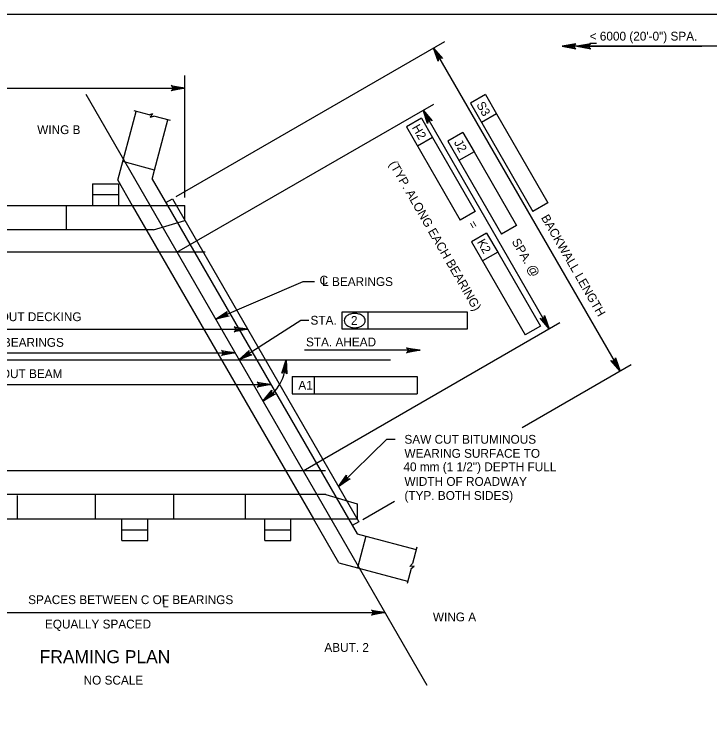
# Model space of a CAD drawing. Extents: x -13 to 81, y -176 to 0.
# Drawn here: x 13.18 to 22.65, y -164.52 to -154.75 of the extents above; entities that cross this region are included whole.
import ezdxf

# ---------------------------------------------------------------- set-up
doc = ezdxf.new("R2010")
doc.units = 0
for name, color, linetype in [('Level 1', 7, 'Continuous'), ('Level 2', 7, 'Continuous'), ('Level 3', 7, 'Continuous'), ('Level 4', 7, 'Continuous')]:
    doc.layers.add(name, color=color, linetype=linetype)

msp = doc.modelspace()

# ---------------------------------------------------------------- linework, layer by layer
at = {"layer": 'Level 1'}
msp.add_lwpolyline([(1.75, -175.25), (33.25, -175.25), (33.25, -154.75), (1.75, -154.75)], close=True, dxfattribs=at)
at = {"layer": 'Level 2'}
for p, q in [((14.5927, -157.0093), (14.8438, -156.0722)), ((15.0924, -156.8711), (15.2755, -156.1879)), ((15.0924, -156.8711), (14.6607, -156.7554)), ((15.06, -156.9921), (15.0924, -156.8711)), ((14.5927, -157.0093), (14.79, -157.3512)), ((15.06, -156.9921), (15.2673, -157.3512)), ((14.2487, -157.0558), (14.2487, -157.3512)), ((14.2487, -157.0558), (14.6031, -157.0558)), ((14.6031, -157.0558), (14.6031, -157.3512)), ((15.2452, -157.3129), (15.3347, -157.2612)), ((15.3347, -157.2612), (17.8734, -161.6584)), ((7.3205, -157.3512), (15.5059, -157.3512)), ((14.79, -157.3512), (17.2547, -161.6202)), ((15.2673, -157.3512), (17.7321, -161.6202)), ((15.5059, -157.5578), (15.5059, -157.3512)), ((15.0767, -157.6833), (15.5059, -157.5578)), ((15.0767, -157.6833), (7.7497, -157.6833)), ((17.4221, -161.288), (10.0952, -161.288)), ((17.4221, -161.288), (17.8513, -161.4135)), ((17.8513, -161.4135), (17.8513, -161.6202)), ((9.6659, -161.6202), (17.8513, -161.6202)), ((14.6453, -161.9155), (14.6453, -161.6202)), ((14.9997, -161.9155), (14.9997, -161.6202)), ((16.5942, -161.9155), (16.5942, -161.6202)), ((16.9485, -161.9155), (16.9485, -161.6202)), ((17.5999, -162.2181), (17.2547, -161.6202)), ((17.7321, -161.6202), (17.8485, -161.822)), ((17.8734, -161.6584), (17.7839, -161.7101)), ((17.8485, -161.822), (17.9695, -161.8544)), ((14.6453, -161.9155), (14.9997, -161.9155)), ((16.5942, -161.9155), (16.9485, -161.9155)), ((17.9695, -161.8544), (17.8538, -162.2862)), ((17.9695, -161.8544), (18.6527, -162.0374)), ((17.5999, -162.2181), (18.537, -162.4692))]:
    msp.add_line(p, q, dxfattribs=at)
at = {"layer": 'Level 3'}
for p, q in [((14.1551, -155.8382), (18.7996, -163.8826)), ((15.0182, -156.119), (14.8132, -156.0641)), ((15.0182, -156.119), (15.0663, -156.0983)), ((15.0663, -156.0983), (15.0334, -156.1482)), ((15.0334, -156.1482), (15.0848, -156.1368)), ((15.3088, -156.1968), (15.0848, -156.1368)), ((14.2487, -157.2035), (14.6031, -157.2035)), ((13.8944, -157.6833), (13.8944, -157.3512)), ((13.2272, -161.6202), (13.2272, -161.3036)), ((14.2902, -161.6202), (14.2902, -161.288)), ((15.354, -161.6202), (15.354, -161.288)), ((16.3284, -161.6202), (16.3284, -161.288)), ((14.6453, -161.7678), (14.9997, -161.7678)), ((16.5942, -161.7678), (16.9485, -161.7678)), ((18.6617, -162.0041), (18.6017, -162.2281)), ((18.5837, -162.2947), (18.5288, -162.4998)), ((18.566, -162.2669), (18.6017, -162.2281)), ((18.6258, -162.2633), (18.566, -162.2669)), ((18.5837, -162.2947), (18.6258, -162.2633))]:
    msp.add_line(p, q, dxfattribs=at)
at = {"layer": 'Level 4'}
for p, q in [((15.388, -157.2305), (19.0423, -155.1207)), ((23.5655, -155.1843), (20.6404, -155.1843)), ((20.9797, -155.1843), (22.5397, -155.1843)), ((21.1059, -155.146), (21.0173, -155.146)), ((18.8889, -155.2092), (21.4276, -159.6064)), ((15.5059, -157.2456), (15.5059, -155.5842)), ((7.3205, -155.7548), (15.5059, -155.7548)), ((19.5953, -155.8435), (19.3908, -155.9616)), ((19.5953, -155.8435), (19.7466, -156.1054)), ((15.3975, -157.99), (18.893, -155.9718)), ((19.3908, -155.9616), (20.2412, -157.4345)), ((20.4622, -159.0314), (18.7463, -156.0565)), ((18.7252, -156.1655), (18.5206, -156.2837)), ((18.7252, -156.1655), (18.8763, -156.4274)), ((19.7466, -156.1054), (19.542, -156.2235)), ((19.7466, -156.1054), (20.4458, -157.3164)), ((18.5206, -156.2837), (19.2521, -157.5507)), ((19.2892, -156.3587), (19.0846, -156.4768)), ((19.2892, -156.3587), (19.4404, -156.6207)), ((18.8763, -156.4274), (18.6717, -156.5456)), ((18.8763, -156.4274), (19.4567, -157.4326)), ((19.0846, -156.4768), (19.8162, -157.7439)), ((19.4404, -156.6207), (19.2358, -156.7387)), ((19.4404, -156.6207), (20.0207, -157.6258)), ((20.4458, -157.3164), (20.2412, -157.4345)), ((19.4567, -157.4326), (19.2521, -157.5507)), ((20.0207, -157.6258), (19.8162, -157.7439)), ((19.6115, -157.7273), (19.4069, -157.8455)), ((19.6115, -157.7273), (19.7627, -157.9892)), ((19.4069, -157.8455), (20.1384, -159.1126)), ((15.7792, -157.99), (3.7627, -157.99)), ((19.7627, -157.9892), (19.5581, -158.1074)), ((19.7627, -157.9892), (20.343, -158.9944)), ((15.9238, -158.9017), (17.1136, -158.3895)), ((17.1136, -158.3895), (17.268, -158.3895)), ((17.6477, -159.0373), (17.6477, -158.8011)), ((17.6477, -158.8011), (17.9977, -158.8011)), ((17.9977, -159.0373), (17.9977, -158.8011)), ((17.9977, -158.8011), (19.3486, -158.8011)), ((19.3486, -158.8011), (19.3486, -159.0373)), ((16.2413, -159.456), (17.0821, -158.915)), ((17.0821, -158.915), (17.1917, -158.915)), ((17.1146, -160.9642), (20.6102, -158.946)), ((20.343, -158.9944), (20.1384, -159.1126)), ((8.2945, -159.0381), (16.3606, -159.0381)), ((19.3486, -159.0373), (17.6477, -159.0373)), ((8.8385, -159.3603), (16.1886, -159.3603)), ((18.7082, -159.3248), (17.1333, -159.3248)), ((6.2433, -159.4554), (18.3055, -159.4554)), ((20.0965, -160.3749), (21.581, -159.5178)), ((16.9645, -159.6822), (17.267, -159.6822)), ((16.9645, -159.6822), (16.9645, -159.9184)), ((17.267, -159.6822), (17.267, -159.9184)), ((17.267, -159.6822), (18.6653, -159.6822)), ((18.6653, -159.6822), (18.6653, -159.9184)), ((8.8488, -159.7914), (16.6762, -159.7914)), ((16.9645, -159.9184), (18.6653, -159.9184)), ((17.5973, -161.1802), (18.2556, -160.5326)), ((18.2556, -160.5326), (18.369, -160.5326)), ((17.4195, -160.9642), (3.7506, -160.9642)), ((17.9267, -161.6276), (18.3561, -161.3797)), ((10.8796, -162.8955), (18.2297, -162.8955))]:
    msp.add_line(p, q, dxfattribs=at)
for points in [[(20.6404, -155.1843), (20.8268, -155.2192), (20.8125, -155.2093), (20.8051, -155.1968), (20.8029, -155.1843), (20.8051, -155.1718), (20.8125, -155.1593), (20.8268, -155.1494), (20.6404, -155.1843), (20.8125, -155.1593), (20.8051, -155.1718), (20.6404, -155.1843), (20.8029, -155.1843), (20.8051, -155.1968), (20.6404, -155.1843), (20.8125, -155.2093)], [(20.8419, -155.1843), (21.0283, -155.2192), (21.014, -155.2093), (21.0066, -155.1968), (21.0044, -155.1843), (21.0066, -155.1718), (21.014, -155.1593), (21.0283, -155.1494), (20.8419, -155.1843), (21.014, -155.1593), (21.0066, -155.1718), (20.8419, -155.1843), (21.0044, -155.1843), (21.0066, -155.1968), (20.8419, -155.1843), (21.014, -155.2093)], [(18.8889, -155.2092), (19.0124, -155.3533), (18.9966, -155.3457), (18.9821, -155.3456), (18.9702, -155.35), (18.9604, -155.3581), (18.9533, -155.3707), (18.9518, -155.3882), (18.8889, -155.2092), (18.9533, -155.3707), (18.9604, -155.3581), (18.8889, -155.2092), (18.9702, -155.35), (18.9821, -155.3456), (18.8889, -155.2092), (18.9966, -155.3457)], [(15.5059, -155.7548), (15.3195, -155.7897), (15.3338, -155.7798), (15.3412, -155.7672), (15.3434, -155.7548), (15.3412, -155.7422), (15.3338, -155.7297), (15.3195, -155.7198), (15.5059, -155.7548), (15.3338, -155.7297), (15.3412, -155.7422), (15.5059, -155.7548), (15.3434, -155.7548), (15.3412, -155.7672), (15.5059, -155.7548), (15.3338, -155.7798)], [(18.7463, -156.0565), (18.8697, -156.2005), (18.8539, -156.1931), (18.8394, -156.1929), (18.8275, -156.1972), (18.8178, -156.2053), (18.8107, -156.218), (18.8092, -156.2354), (18.7463, -156.0565), (18.8107, -156.218), (18.8178, -156.2053), (18.7463, -156.0565), (18.8275, -156.1972), (18.8394, -156.1929), (18.7463, -156.0565), (18.8539, -156.1931)], [(15.9238, -158.9017), (16.0813, -158.7959), (16.072, -158.8107), (16.0701, -158.8252), (16.0731, -158.8375), (16.08, -158.8481), (16.0918, -158.8567), (16.1088, -158.8602), (15.9238, -158.9017), (16.0918, -158.8567), (16.08, -158.8481), (15.9238, -158.9017), (16.0731, -158.8375), (16.0701, -158.8252), (15.9238, -158.9017), (16.072, -158.8107)], [(20.4622, -159.0314), (20.3388, -158.8874), (20.3546, -158.8948), (20.3691, -158.895), (20.381, -158.8907), (20.3908, -158.8826), (20.3978, -158.8699), (20.3993, -158.8525), (20.4622, -159.0314), (20.3978, -158.8699), (20.3908, -158.8826), (20.4622, -159.0314), (20.381, -158.8907), (20.3691, -158.895), (20.4622, -159.0314), (20.3546, -158.8948)], [(16.3606, -159.0381), (16.1742, -159.073), (16.1885, -159.0631), (16.1959, -159.0506), (16.1981, -159.0381), (16.1959, -159.0256), (16.1885, -159.0131), (16.1742, -159.0032), (16.3606, -159.0381), (16.1885, -159.0131), (16.1959, -159.0256), (16.3606, -159.0381), (16.1981, -159.0381), (16.1959, -159.0506), (16.3606, -159.0381), (16.1885, -159.0631)], [(18.7082, -159.3248), (18.5218, -159.3597), (18.5362, -159.3498), (18.5436, -159.3373), (18.5457, -159.3248), (18.5436, -159.3123), (18.5362, -159.2998), (18.5218, -159.2899), (18.7082, -159.3248), (18.5362, -159.2998), (18.5436, -159.3123), (18.7082, -159.3248), (18.5457, -159.3248), (18.5436, -159.3373), (18.7082, -159.3248), (18.5362, -159.3498)], [(16.1886, -159.3603), (16.0022, -159.3952), (16.0165, -159.3852), (16.0239, -159.3727), (16.0261, -159.3603), (16.0239, -159.3477), (16.0165, -159.3353), (16.0022, -159.3253), (16.1886, -159.3603), (16.0165, -159.3353), (16.0239, -159.3477), (16.1886, -159.3603), (16.0261, -159.3603), (16.0239, -159.3727), (16.1886, -159.3603), (16.0165, -159.3852)], [(16.2413, -159.456), (16.3791, -159.3257), (16.3724, -159.3419), (16.3729, -159.3564), (16.3779, -159.3681), (16.3865, -159.3774), (16.3995, -159.3839), (16.4169, -159.3845), (16.2413, -159.456), (16.3995, -159.3839), (16.3865, -159.3774), (16.2413, -159.456), (16.3779, -159.3681), (16.3729, -159.3564), (16.2413, -159.456), (16.3724, -159.3419)], [(16.8819, -159.4554), (16.8919, -159.6447), (16.884, -159.6293), (16.8726, -159.6202), (16.8604, -159.6165), (16.8478, -159.6169), (16.8344, -159.6227), (16.8227, -159.6355), (16.8819, -159.4554), (16.8344, -159.6227), (16.8478, -159.6169), (16.8819, -159.4554), (16.8604, -159.6165), (16.8726, -159.6202), (16.8819, -159.4554), (16.884, -159.6293)], [(21.4276, -159.6064), (21.3041, -159.4624), (21.3199, -159.4699), (21.3344, -159.4701), (21.3463, -159.4657), (21.3561, -159.4576), (21.3633, -159.4449), (21.3647, -159.4275), (21.4276, -159.6064), (21.3633, -159.4449), (21.3561, -159.4576), (21.4276, -159.6064), (21.3463, -159.4657), (21.3344, -159.4701), (21.4276, -159.6064), (21.3199, -159.4699)], [(16.6762, -159.7914), (16.4898, -159.8263), (16.5042, -159.8164), (16.5116, -159.8039), (16.5137, -159.7914), (16.5116, -159.7789), (16.5042, -159.7664), (16.4898, -159.7565), (16.6762, -159.7914), (16.5042, -159.7664), (16.5116, -159.7789), (16.6762, -159.7914), (16.5137, -159.7914), (16.5116, -159.8039), (16.6762, -159.7914), (16.5042, -159.8164)], [(16.5667, -160.0152), (16.687, -159.8686), (16.6824, -159.8854), (16.6848, -159.8998), (16.6912, -159.9108), (16.7009, -159.919), (16.7146, -159.9237), (16.732, -159.9221), (16.5667, -160.0152), (16.7146, -159.9237), (16.7009, -159.919), (16.5667, -160.0152), (16.6912, -159.9108), (16.6848, -159.8998), (16.5667, -160.0152), (16.6824, -159.8854)], [(17.5973, -161.1802), (17.7057, -161.0245), (17.7024, -161.0417), (17.7059, -161.0557), (17.7132, -161.0662), (17.7235, -161.0736), (17.7375, -161.0773), (17.7547, -161.0743), (17.5973, -161.1802), (17.7375, -161.0773), (17.7235, -161.0736), (17.5973, -161.1802), (17.7132, -161.0662), (17.7059, -161.0557), (17.5973, -161.1802), (17.7024, -161.0417)], [(18.2297, -162.8955), (18.0433, -162.9304), (18.0576, -162.9205), (18.065, -162.908), (18.0672, -162.8955), (18.065, -162.883), (18.0576, -162.8705), (18.0433, -162.8606), (18.2297, -162.8955), (18.0576, -162.8705), (18.065, -162.883), (18.2297, -162.8955), (18.0672, -162.8955), (18.065, -162.908), (18.2297, -162.8955), (18.0576, -162.9205)]]:
    msp.add_lwpolyline(points, dxfattribs=at)
for points in [[(18.965, -155.3017), (18.9309, -155.3214), (18.8889, -155.2092)], [(18.7867, -156.1642), (18.8194, -156.1453), (18.7463, -156.0565)], [(20.3892, -158.9427), (20.4219, -158.9237), (20.4622, -159.0314)], [(21.3856, -159.4942), (21.3515, -159.5139), (21.4276, -159.6064)], [(17.7054, -161.1003), (17.6789, -161.0733), (17.6113, -161.1663)]]:
    msp.add_lwpolyline(points, close=True, dxfattribs=at)
for centre, radius, start, end in [((17.7409, -158.9197), 0.067, 148.55069, 180), ((17.7774, -158.9421), 0.1099, 124.10897, 148.55069), ((17.8014, -158.9775), 0.1526, 105.67084, 124.10897), ((17.8171, -159.0335), 0.2108, 90, 105.67084), ((17.8171, -159.0335), 0.2108, 74.32916, 90), ((17.8328, -158.9775), 0.1526, 55.89103, 74.32916), ((17.8568, -158.9421), 0.1099, 31.44931, 55.89103), ((17.8933, -158.9197), 0.067, 0, 31.44931), ((17.7409, -158.9197), 0.067, 180, 211.44931), ((17.7774, -158.8974), 0.1099, 211.44931, 235.89103), ((17.8014, -158.8619), 0.1526, 235.89103, 254.32916), ((17.8328, -158.8619), 0.1526, 285.67084, 304.10897), ((17.8568, -158.8974), 0.1099, 304.10897, 328.55069), ((17.8933, -158.9197), 0.067, 328.55069, 0), ((17.8171, -158.806), 0.2108, 254.32916, 270), ((17.8171, -158.806), 0.2108, 270, 285.67084), ((16.2514, -159.469), 0.6307, 299.99965, 1.23524)]:
    msp.add_arc(centre, radius, start, end, dxfattribs=at)

# ---------------------------------------------------------------- texts
for s, height, p in [('< 6000 (20\'-0") SPA.', 0.12, (21.0143, -155.1068)), ('WING B', 0.12, (13.4953, -156.3804)), ('C', 0.1209, (17.3377, -158.4303)), ('L BEARINGS', 0.12, (17.3739, -158.449)), ('OUT TO OUT DECKING', 0.12, (12.3339, -158.9272)), ('STA.', 0.12, (17.2149, -158.9753)), ('2', 0.12, (17.7651, -158.978)), ('C/C BEARINGS', 0.12, (12.708, -159.2767)), ('STA. AHEAD', 0.12, (17.1536, -159.2712)), ('OUT TO OUT BEAM', 0.12, (12.3501, -159.7028)), ('SAW CUT BITUMINOUS', 0.12, (18.4934, -160.5965)), ('WEARING SURFACE TO ', 0.12, (18.4934, -160.7877)), ('40 mm (1 1/2") DEPTH FULL', 0.12, (18.4797, -160.9705)), ('WIDTH OF ROADWAY', 0.12, (18.4934, -161.1702)), ('(TYP. BOTH SIDES)', 0.12, (18.4934, -161.3614)), ('SPACES BETWEEN C OF BEARINGS', 0.12, (13.3726, -162.7802)), ('L', 0.12, (15.197, -162.8252)), ('WING A', 0.12, (18.8806, -163.0148)), ('EQUALLY SPACED', 0.12, (13.6005, -163.1122)), ('ABUT. 2', 0.12, (17.4037, -163.4303)), ('FRAMING PLAN', 0.177167, (13.5295, -163.5845)), ('NO SCALE', 0.12, (14.127, -163.876))]:
    msp.add_text(s, height=height, dxfattribs=at).set_placement(p)
for s, height, rotation, p in [('S3', 0.12, 299.93822, (19.4688, -155.9803)), ('H2', 0.12, 299.93822, (18.5918, -156.2905)), ('J2', 0.12, 299.93822, (19.1628, -156.496)), ('(TYP. ALONG EACH BEARING)', 0.12, 299.97452, (18.2787, -156.7855)), ('BACKWALL LENGTH', 0.12, 299.97452, (20.3492, -157.5181)), ('= ', 0.11811, 299.97452, (19.357, -157.6023)), ('K2', 0.12, 299.93822, (19.4773, -157.8512)), ('SPA. @', 0.12, 299.97452, (19.9503, -157.8432)), ('A1', 0.12, 359.93823, (17.0495, -159.8603))]:
    msp.add_text(s, height=height, rotation=rotation, dxfattribs=at).set_placement(p)

doc.saveas('drawing.dxf')
